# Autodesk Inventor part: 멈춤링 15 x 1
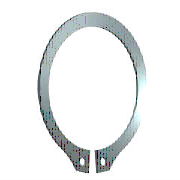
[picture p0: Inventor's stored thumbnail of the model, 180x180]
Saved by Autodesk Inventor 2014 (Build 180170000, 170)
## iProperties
IsCustomPart: 1
Created: 2012-02
Part Number: 멈춤링 15 x 1
Material: 강철, 연강
Description: 리테이닝 링(C형)
Document SubType Name: Modeling
Standard: KS B 1336
Designer: mduedu
Standards Organization: KS
Language: ko-KR
Size Designation: 15 x 1
Categories: <MemberInstance><Categories><Category DisplayName="샤프트 부품" InternalName="7f7aeb1f-a693-4053-b835-cee3144e0d98" Mnemonic="SHFT"><Category DisplayName="써클립" Inter
Density: 1 g/cm^3
Appearance: 파란색 - 벽 페인트 - 광택
Author: mduedu
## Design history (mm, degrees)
sketch "스케치1"
  geometry: L1 (-6, 0)-(6, 0) reference; L2 (0, 20.189)-(0, -80.536) reference; L3 (-48.09, 0)-(48.09, 0) reference; L4 (-0.425, -14.637)-(-0.425, -18.137); L5 (-0.425, -6.54)-(-0.425, -13.29); L6 (-2.795, 2.1)-(3.672, 2.1); L7 (0.425, -6.54)-(0.425, -13.29); L8 (0.425, -14.637)-(0.425, -18.137); C1 r 0.85 at (-1.7, -16.283); C2 r 0.85 at (1.7, -16.283); A1 r 7.15 centre (0, -7.5) between (0.425, -14.637) and (-0.425, -14.637); A2 r 9.075 centre (0, -6.975) between (4.291, -14.971) and (-4.291, -14.971); A3 r 10.646 centre (0, -7.5) between (-2.023, -17.952) and (-0.425, -18.137); A4 r 1.7 centre (-1.7, -16.283) between (-3.397, -16.376) and (-2.023, -17.952); A5 r 1.7 centre (-5.095, -16.469) between (-3.397, -16.376) and (-4.291, -14.971); A6 r 1.7 centre (5.095, -16.469) between (4.291, -14.971) and (3.397, -16.376); A7 r 1.7 centre (1.7, -16.283) between (2.023, -17.952) and (3.397, -16.376); A8 r 10.646 centre (0, -7.5) between (0.425, -18.137) and (2.023, -17.952)
  constraints: 16 point on circle, 12 end point, 10 centre point, 9 symmetric about line, 5 point on line, 4 tangent, 3 coincident, 2 horizontal, 1 perpendicular, 1 vertical, 5 other
  dimensions: "d0" = 14.3 diameter of A1 (= ND); "d1" = 3.5 distance of L4.end L4.start (= SRB2); "d6" = 0.425 distance between parallel lines of L2 L5 (= 0.25 x SD5); "d7" = 2.1 distance between parallel lines of L6 L3 (= SRB1); "d8" = 0.525 distance of A1.centre A2.centre (= 0.25 x SRB1); "d9" = 1.7 radius of A4 (= SD5); "d10" = 1.7 radius of A5 (= SD5); "d11" = 1.275 distance from line of L4 A4.centre (= 0.75 x SD5); "d12" = 1.7 diameter of C1 (= SD5); "d13" = 1.7 diameter of C2 (= SD5); "d14" = 7.5 distance from line of A1.centre L1 (= 0.5 x WD)
extrude "본체" new body sketch "스케치1" distance "d2" = 1 (= SD); taper "d3" = 0 deg
workaxis "Work Axis1"
workplane "Work Plane1"
body "Solid1"
other parameters: "WD" = 15 (= WDMIN) [user parameter; used in 1 equation term], "SD" = 1 [user parameter; used in 1 equation term], "SRB1" = 2.1 [user parameter; used in 2 equation terms], "ND" = 14.3 [user parameter; used in 1 equation term], "SRB2" = 3.5 [user parameter; used in 1 equation term], "SD5" = 1.7 [user parameter; used in 6 equation terms], "d15" = 0, "d16" = 0, "d17" = 0, "d41" = 0, "d42" = 0, "WDMIN" = 15 [user parameter; used in 1 equation term], "SD3" = 13.8 [user parameter], "WDMAX" = 16 [user parameter]
